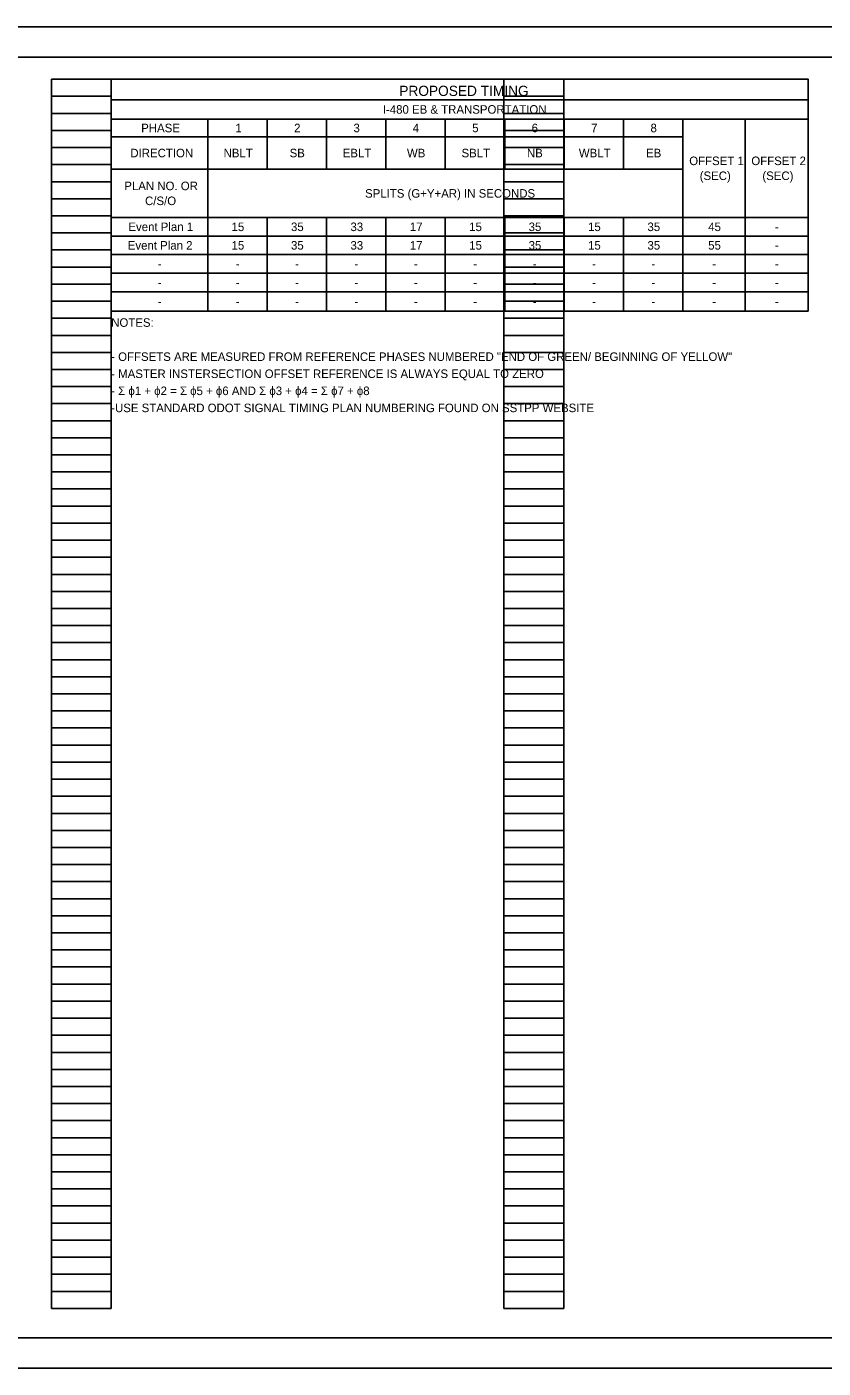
# Model space of a CAD drawing. Extents: x 0 to 40.3, y -1.2 to 22.
# Drawn here: x 15.86 to 28.91, y 0 to 22 of the extents above; entities that cross this region are included whole.
import ezdxf

# ---------------------------------------------------------------- set-up
doc = ezdxf.new("R2010")
doc.units = 0
for name, color, linetype in [('SH_Border', 7, 'Continuous'), ('SH_Cut_Line', 7, 'Continuous'), ('SH_Data', 7, 'Continuous'), ('SH_Text', 7, 'Continuous')]:
    doc.layers.add(name, color=color, linetype=linetype)

msp = doc.modelspace()

# ---------------------------------------------------------------- linework, layer by layer
at = {"layer": 'SH_Border'}
msp.add_lwpolyline([(1.5, 21.5), (33.5, 21.5), (33.5, 0.5), (1.5, 0.5)], close=True, dxfattribs=at)
at = {"layer": 'SH_Cut_Line'}
msp.add_lwpolyline([(0, 0), (34, 0), (34, 22), (0, 22)], close=True, dxfattribs=at)
at = {"layer": 'SH_Data'}
for p, q in [((16.26, 0.98), (16.26, 21.14)), ((16.26, 21.14), (17.24, 21.14)), ((17.24, 0.98), (17.24, 21.14)), ((23.68, 0.98), (23.68, 21.14)), ((23.68, 21.14), (24.66, 21.14)), ((24.66, 0.98), (24.66, 21.14)), ((16.26, 20.86), (17.24, 20.86)), ((23.68, 20.86), (24.66, 20.86)), ((16.26, 20.58), (17.24, 20.58)), ((23.68, 20.58), (24.66, 20.58)), ((16.26, 20.3), (17.24, 20.3)), ((23.68, 20.3), (24.66, 20.3)), ((16.26, 20.02), (17.24, 20.02)), ((23.68, 20.02), (24.66, 20.02)), ((16.26, 19.74), (17.24, 19.74)), ((23.68, 19.74), (24.66, 19.74)), ((16.26, 19.46), (17.24, 19.46)), ((23.68, 19.46), (24.66, 19.46)), ((16.26, 19.18), (17.24, 19.18)), ((23.68, 19.18), (24.66, 19.18)), ((16.26, 18.9), (17.24, 18.9)), ((23.68, 18.9), (24.66, 18.9)), ((16.26, 18.62), (17.24, 18.62)), ((23.68, 18.62), (24.66, 18.62)), ((16.26, 18.34), (17.24, 18.34)), ((23.68, 18.34), (24.66, 18.34)), ((16.26, 18.06), (17.24, 18.06)), ((23.68, 18.06), (24.66, 18.06)), ((16.26, 17.78), (17.24, 17.78)), ((23.68, 17.78), (24.66, 17.78)), ((16.26, 17.5), (17.24, 17.5)), ((23.68, 17.5), (24.66, 17.5)), ((16.26, 17.22), (17.24, 17.22)), ((23.68, 17.22), (24.66, 17.22)), ((16.26, 16.94), (17.24, 16.94)), ((23.68, 16.94), (24.66, 16.94)), ((16.26, 16.66), (17.24, 16.66)), ((23.68, 16.66), (24.66, 16.66)), ((16.26, 16.38), (17.24, 16.38)), ((23.68, 16.38), (24.66, 16.38)), ((16.26, 16.1), (17.24, 16.1)), ((23.68, 16.1), (24.66, 16.1)), ((16.26, 15.82), (17.24, 15.82)), ((23.68, 15.82), (24.66, 15.82)), ((16.26, 15.54), (17.24, 15.54)), ((23.68, 15.54), (24.66, 15.54)), ((16.26, 15.26), (17.24, 15.26)), ((23.68, 15.26), (24.66, 15.26)), ((16.26, 14.98), (17.24, 14.98)), ((23.68, 14.98), (24.66, 14.98)), ((16.26, 14.7), (17.24, 14.7)), ((23.68, 14.7), (24.66, 14.7)), ((16.26, 14.42), (17.24, 14.42)), ((23.68, 14.42), (24.66, 14.42)), ((16.26, 14.14), (17.24, 14.14)), ((23.68, 14.14), (24.66, 14.14)), ((16.26, 13.86), (17.24, 13.86)), ((23.68, 13.86), (24.66, 13.86)), ((16.26, 13.58), (17.24, 13.58)), ((23.68, 13.58), (24.66, 13.58)), ((16.26, 13.3), (17.24, 13.3)), ((23.68, 13.3), (24.66, 13.3)), ((16.26, 13.02), (17.24, 13.02)), ((23.68, 13.02), (24.66, 13.02)), ((16.26, 12.74), (17.24, 12.74)), ((23.68, 12.74), (24.66, 12.74)), ((16.26, 12.46), (17.24, 12.46)), ((23.68, 12.46), (24.66, 12.46)), ((16.26, 12.18), (17.24, 12.18)), ((23.68, 12.18), (24.66, 12.18)), ((16.26, 11.9), (17.24, 11.9)), ((23.68, 11.9), (24.66, 11.9)), ((16.26, 11.62), (17.24, 11.62)), ((23.68, 11.62), (24.66, 11.62)), ((16.26, 11.34), (17.24, 11.34)), ((23.68, 11.34), (24.66, 11.34)), ((16.26, 11.06), (17.24, 11.06)), ((23.68, 11.06), (24.66, 11.06)), ((16.26, 10.78), (17.24, 10.78)), ((23.68, 10.78), (24.66, 10.78)), ((16.26, 10.5), (17.24, 10.5)), ((23.68, 10.5), (24.66, 10.5)), ((16.26, 10.22), (17.24, 10.22)), ((23.68, 10.22), (24.66, 10.22)), ((16.26, 9.94), (17.24, 9.94)), ((23.68, 9.94), (24.66, 9.94)), ((16.26, 9.66), (17.24, 9.66)), ((23.68, 9.66), (24.66, 9.66)), ((16.26, 9.38), (17.24, 9.38)), ((23.68, 9.38), (24.66, 9.38)), ((16.26, 9.1), (17.24, 9.1)), ((23.68, 9.1), (24.66, 9.1)), ((16.26, 8.82), (17.24, 8.82)), ((23.68, 8.82), (24.66, 8.82)), ((16.26, 8.54), (17.24, 8.54)), ((23.68, 8.54), (24.66, 8.54)), ((16.26, 8.26), (17.24, 8.26)), ((23.68, 8.26), (24.66, 8.26)), ((16.26, 7.98), (17.24, 7.98)), ((23.68, 7.98), (24.66, 7.98)), ((16.26, 7.7), (17.24, 7.7)), ((23.68, 7.7), (24.66, 7.7)), ((16.26, 7.42), (17.24, 7.42)), ((23.68, 7.42), (24.66, 7.42)), ((16.26, 7.14), (17.24, 7.14)), ((23.68, 7.14), (24.66, 7.14)), ((16.26, 6.86), (17.24, 6.86)), ((23.68, 6.86), (24.66, 6.86)), ((16.26, 6.58), (17.24, 6.58)), ((23.68, 6.58), (24.66, 6.58)), ((16.26, 6.3), (17.24, 6.3)), ((23.68, 6.3), (24.66, 6.3)), ((16.26, 6.02), (17.24, 6.02)), ((23.68, 6.02), (24.66, 6.02)), ((16.26, 5.74), (17.24, 5.74)), ((23.68, 5.74), (24.66, 5.74)), ((16.26, 5.46), (17.24, 5.46)), ((23.68, 5.46), (24.66, 5.46)), ((16.26, 5.18), (17.24, 5.18)), ((23.68, 5.18), (24.66, 5.18)), ((16.26, 4.9), (17.24, 4.9)), ((23.68, 4.9), (24.66, 4.9)), ((16.26, 4.62), (17.24, 4.62)), ((23.68, 4.62), (24.66, 4.62)), ((16.26, 4.34), (17.24, 4.34)), ((23.68, 4.34), (24.66, 4.34)), ((16.26, 4.06), (17.24, 4.06)), ((23.68, 4.06), (24.66, 4.06)), ((16.26, 3.78), (17.24, 3.78)), ((23.68, 3.78), (24.66, 3.78)), ((16.26, 3.5), (17.24, 3.5)), ((23.68, 3.5), (24.66, 3.5)), ((16.26, 3.22), (17.24, 3.22)), ((23.68, 3.22), (24.66, 3.22)), ((16.26, 2.94), (17.24, 2.94)), ((23.68, 2.94), (24.66, 2.94)), ((16.26, 2.66), (17.24, 2.66)), ((23.68, 2.66), (24.66, 2.66)), ((16.26, 2.38), (17.24, 2.38)), ((23.68, 2.38), (24.66, 2.38)), ((16.26, 2.1), (17.24, 2.1)), ((23.68, 2.1), (24.66, 2.1)), ((16.26, 1.82), (17.24, 1.82)), ((23.68, 1.82), (24.66, 1.82)), ((16.26, 1.54), (17.24, 1.54)), ((23.68, 1.54), (24.66, 1.54)), ((16.26, 1.26), (17.24, 1.26)), ((23.68, 1.26), (24.66, 1.26)), ((16.26, 0.98), (17.24, 0.98)), ((23.68, 0.98), (24.66, 0.98))]:
    msp.add_line(p, q, dxfattribs=at)
at = {"layer": 'SH_Text'}
for p, q in [((17.24, 21.14), (28.668, 21.14)), ((17.24, 21.14), (17.24, 17.336)), ((28.668, 21.14), (28.668, 17.336)), ((17.24, 20.805), (28.668, 20.805)), ((17.24, 20.486), (28.668, 20.486)), ((18.823, 20.486), (18.823, 17.336)), ((19.797, 20.486), (19.797, 19.664)), ((20.77, 20.486), (20.77, 19.664)), ((21.744, 20.486), (21.744, 19.664)), ((22.718, 20.486), (22.718, 19.664)), ((23.692, 20.486), (23.692, 19.664)), ((24.666, 20.486), (24.666, 19.664)), ((25.64, 20.486), (25.64, 19.664)), ((26.614, 20.486), (26.614, 17.336)), ((27.633, 20.486), (27.633, 17.336)), ((17.24, 20.197), (26.614, 20.197)), ((17.24, 19.664), (18.823, 19.664)), ((18.823, 19.664), (26.614, 19.664)), ((17.24, 18.873), (28.668, 18.873)), ((19.797, 18.873), (19.797, 17.336)), ((20.77, 18.873), (20.77, 17.336)), ((21.744, 18.873), (21.744, 17.336)), ((22.718, 18.873), (22.718, 17.336)), ((23.692, 18.873), (23.692, 17.336)), ((24.666, 18.873), (24.666, 17.336)), ((25.64, 18.873), (25.64, 17.336)), ((17.24, 18.568), (28.668, 18.568)), ((17.24, 18.264), (28.668, 18.264)), ((17.24, 17.96), (28.668, 17.96)), ((17.24, 17.655), (28.668, 17.655)), ((17.24, 17.336), (28.668, 17.336))]:
    msp.add_line(p, q, dxfattribs=at)
for points in [[(17.24, 21.14), (28.668, 21.14), (28.668, 20.805), (17.24, 20.805)], [(17.24, 20.805), (28.668, 20.805), (28.668, 20.486), (17.24, 20.486)]]:
    msp.add_lwpolyline(points, close=True, dxfattribs=at)

# ---------------------------------------------------------------- texts
for s, height, p in [('PROPOSED TIMING', 0.168, (21.963, 20.866)), ('I-480 EB & TRANSPORTATION', 0.14, (21.693, 20.575)), ('PHASE', 0.14, (17.732, 20.271)), ('1', 0.14, (19.275, 20.271)), ('2', 0.14, (20.239, 20.271)), ('3', 0.14, (21.212, 20.271)), ('4', 0.14, (22.184, 20.271)), ('5', 0.14, (23.159, 20.271)), ('6', 0.14, (24.133, 20.271)), ('7', 0.14, (25.108, 20.271)), ('8', 0.14, (26.082, 20.271)), ('DIRECTION', 0.14, (17.554, 19.86)), ('NBLT', 0.14, (19.083, 19.86)), ('SB', 0.14, (20.165, 19.86)), ('EBLT', 0.14, (21.036, 19.86)), ('WB', 0.14, (22.089, 19.86)), ('SBLT', 0.14, (22.984, 19.86)), ('NB', 0.14, (24.056, 19.86)), ('WBLT', 0.14, (24.907, 19.86)), ('EB', 0.14, (26.009, 19.86)), ('OFFSET 1 ', 0.14, (26.717, 19.732)), ('OFFSET 2 ', 0.14, (27.735, 19.732)), ('(SEC)', 0.14, (26.889, 19.487)), ('(SEC)', 0.14, (27.916, 19.487)), ('PLAN NO. OR ', 0.14, (17.455, 19.321)), ('C/S/O', 0.14, (17.795, 19.076)), ('SPLITS (G+Y+AR) IN SECONDS', 0.14, (21.402, 19.198)), ('Event Plan 1', 0.14, (17.522, 18.65)), ('15', 0.14, (19.214, 18.65)), ('35', 0.14, (20.188, 18.65)), ('33', 0.14, (21.163, 18.65)), ('17', 0.14, (22.137, 18.65)), ('15', 0.14, (23.11, 18.65)), ('35', 0.14, (24.084, 18.65)), ('15', 0.14, (25.058, 18.65)), ('35', 0.14, (26.032, 18.65)), ('45', 0.14, (27.028, 18.65)), ('-', 0.14, (28.122, 18.65)), ('Event Plan 2', 0.14, (17.512, 18.346)), ('15', 0.14, (19.214, 18.346)), ('35', 0.14, (20.188, 18.346)), ('33', 0.14, (21.163, 18.346)), ('17', 0.14, (22.137, 18.346)), ('15', 0.14, (23.11, 18.346)), ('35', 0.14, (24.084, 18.346)), ('15', 0.14, (25.058, 18.346)), ('35', 0.14, (26.032, 18.346)), ('55', 0.14, (27.028, 18.346)), ('-', 0.14, (28.122, 18.346)), ('-', 0.14, (18.003, 18.042)), ('-', 0.14, (19.281, 18.042)), ('-', 0.14, (20.255, 18.042)), ('-', 0.14, (21.229, 18.042)), ('-', 0.14, (22.203, 18.042)), ('-', 0.14, (23.177, 18.042)), ('-', 0.14, (24.15, 18.042)), ('-', 0.14, (25.124, 18.042)), ('-', 0.14, (26.098, 18.042)), ('-', 0.14, (27.095, 18.042)), ('-', 0.14, (28.122, 18.042)), ('-', 0.14, (18.003, 17.737)), ('-', 0.14, (19.281, 17.737)), ('-', 0.14, (20.255, 17.737)), ('-', 0.14, (21.229, 17.737)), ('-', 0.14, (22.203, 17.737)), ('-', 0.14, (23.177, 17.737)), ('-', 0.14, (24.15, 17.737)), ('-', 0.14, (25.124, 17.737)), ('-', 0.14, (26.098, 17.737)), ('-', 0.14, (27.095, 17.737)), ('-', 0.14, (28.122, 17.737)), ('-', 0.14, (18.003, 17.425)), ('-', 0.14, (19.281, 17.425)), ('-', 0.14, (20.255, 17.425)), ('-', 0.14, (21.229, 17.425)), ('-', 0.14, (22.203, 17.425)), ('-', 0.14, (23.177, 17.425)), ('-', 0.14, (24.15, 17.425)), ('-', 0.14, (25.124, 17.425)), ('-', 0.14, (26.098, 17.425)), ('-', 0.14, (27.095, 17.425)), ('-', 0.14, (28.122, 17.425)), ('NOTES:', 0.14, (17.24, 17.08)), ('- OFFSETS ARE MEASURED FROM REFERENCE PHASES NUMBERED "END OF GREEN/ BEGINNING OF YELLOW"', 0.14, (17.24, 16.52)), ('- MASTER INSTERSECTION OFFSET REFERENCE IS ALWAYS EQUAL TO ZERO', 0.14, (17.24, 16.24)), ('- Σ ϕ1 + ϕ2 = Σ ϕ5 + ϕ6 AND Σ ϕ3 + ϕ4 = Σ ϕ7 + ϕ8', 0.14, (17.24, 15.96)), ('-USE STANDARD ODOT SIGNAL TIMING PLAN NUMBERING FOUND ON SSTPP WEBSITE', 0.14, (17.24, 15.68))]:
    msp.add_text(s, height=height, dxfattribs=at).set_placement(p)

doc.saveas('drawing.dxf')
